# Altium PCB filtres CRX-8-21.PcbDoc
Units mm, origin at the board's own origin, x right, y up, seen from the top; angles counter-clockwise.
Board outline 63.46 x 63.5 mm, 2 copper layers (TopLayer, BottomLayer), stack 1.535 mm thick; 11 components, 6 nets, 58 pads, 970 vias.
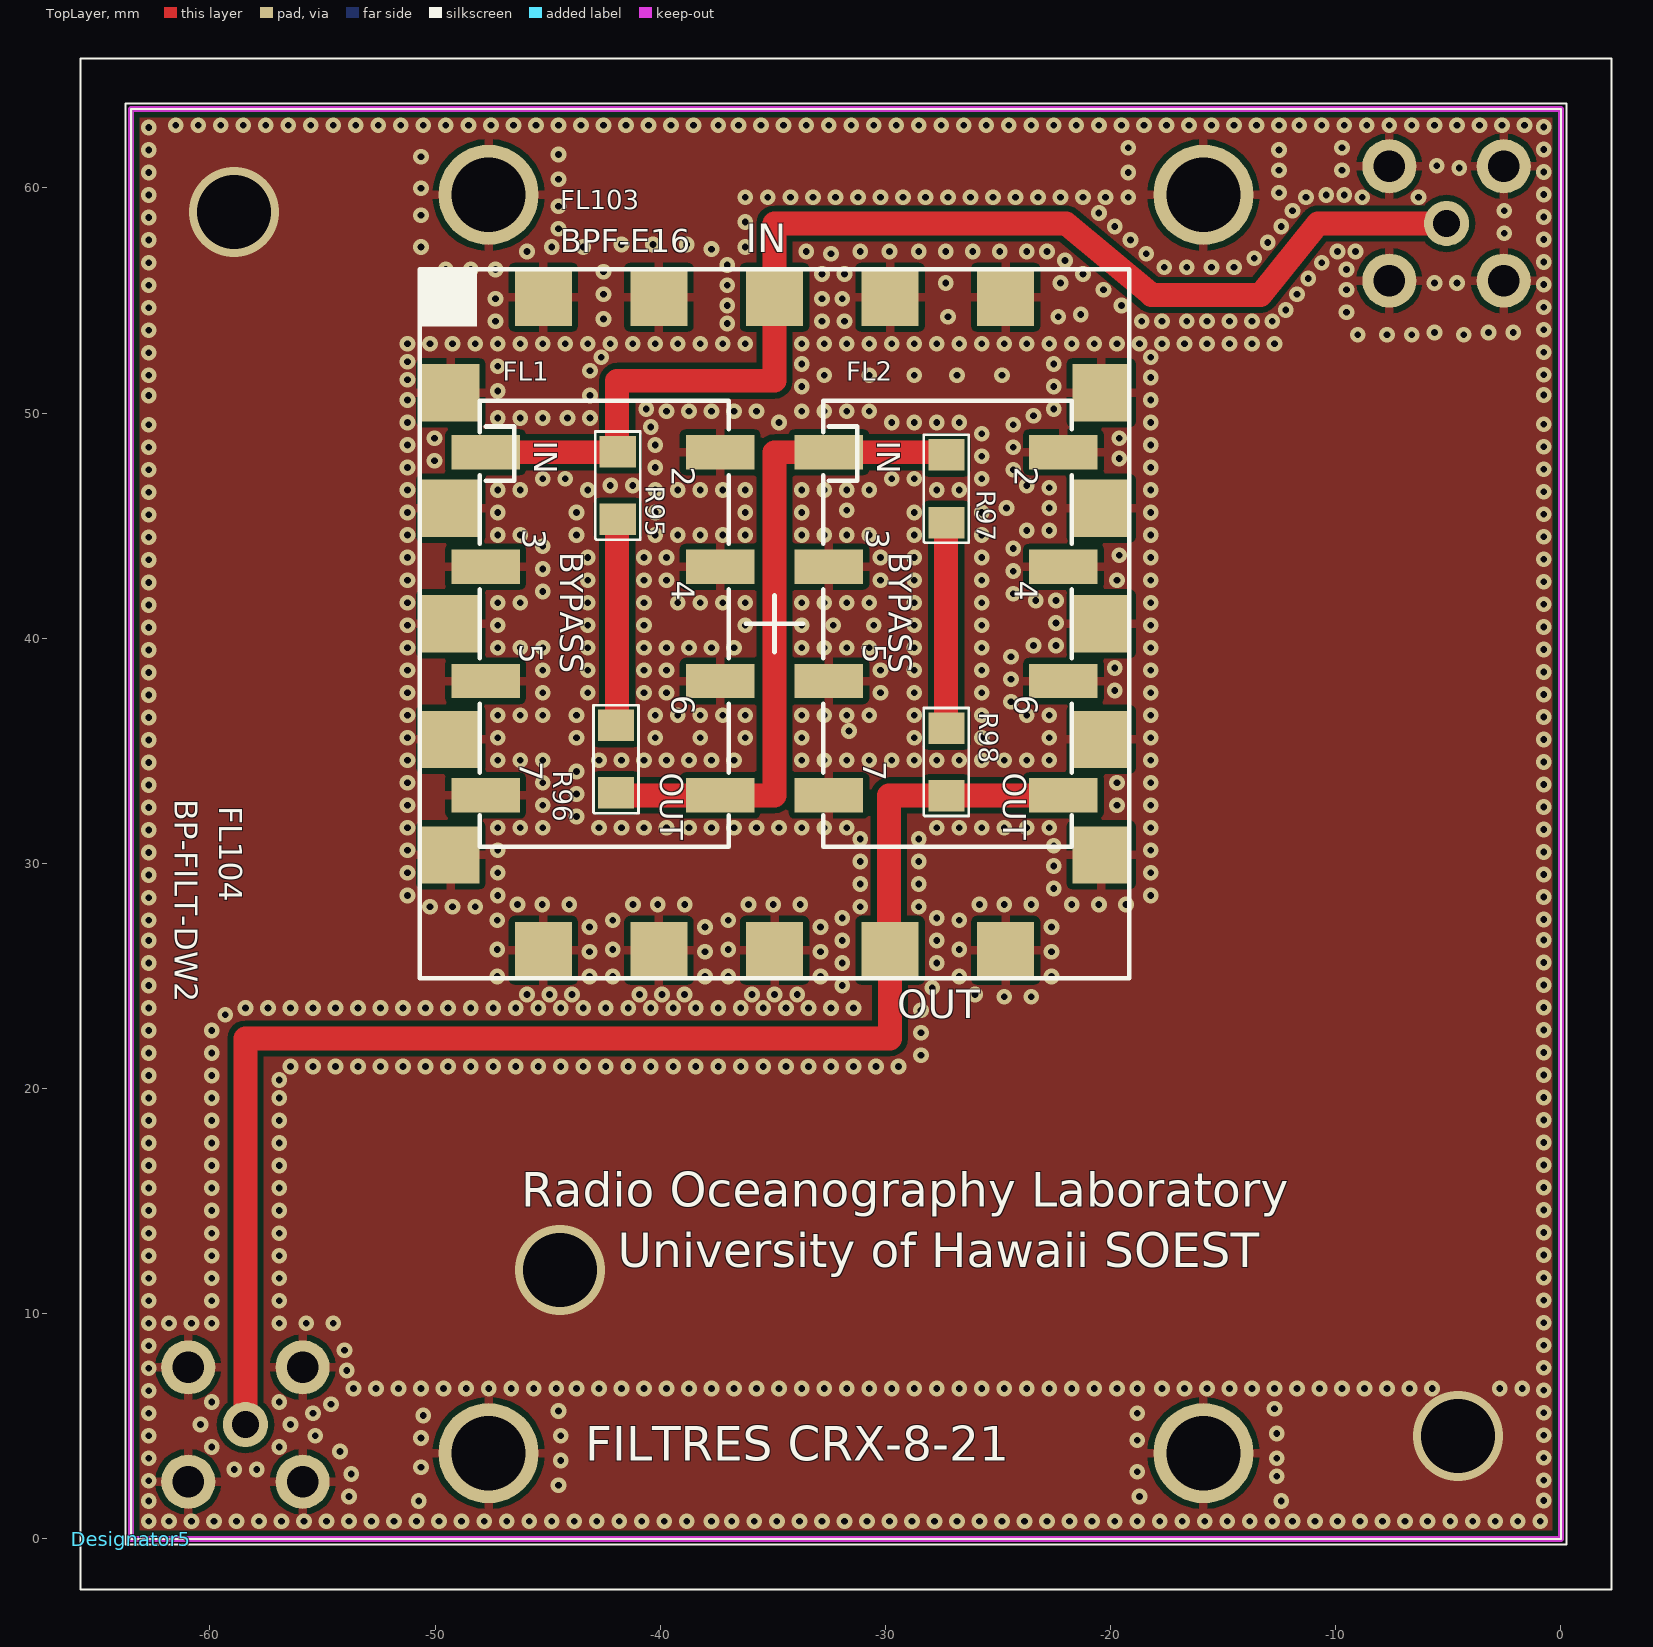
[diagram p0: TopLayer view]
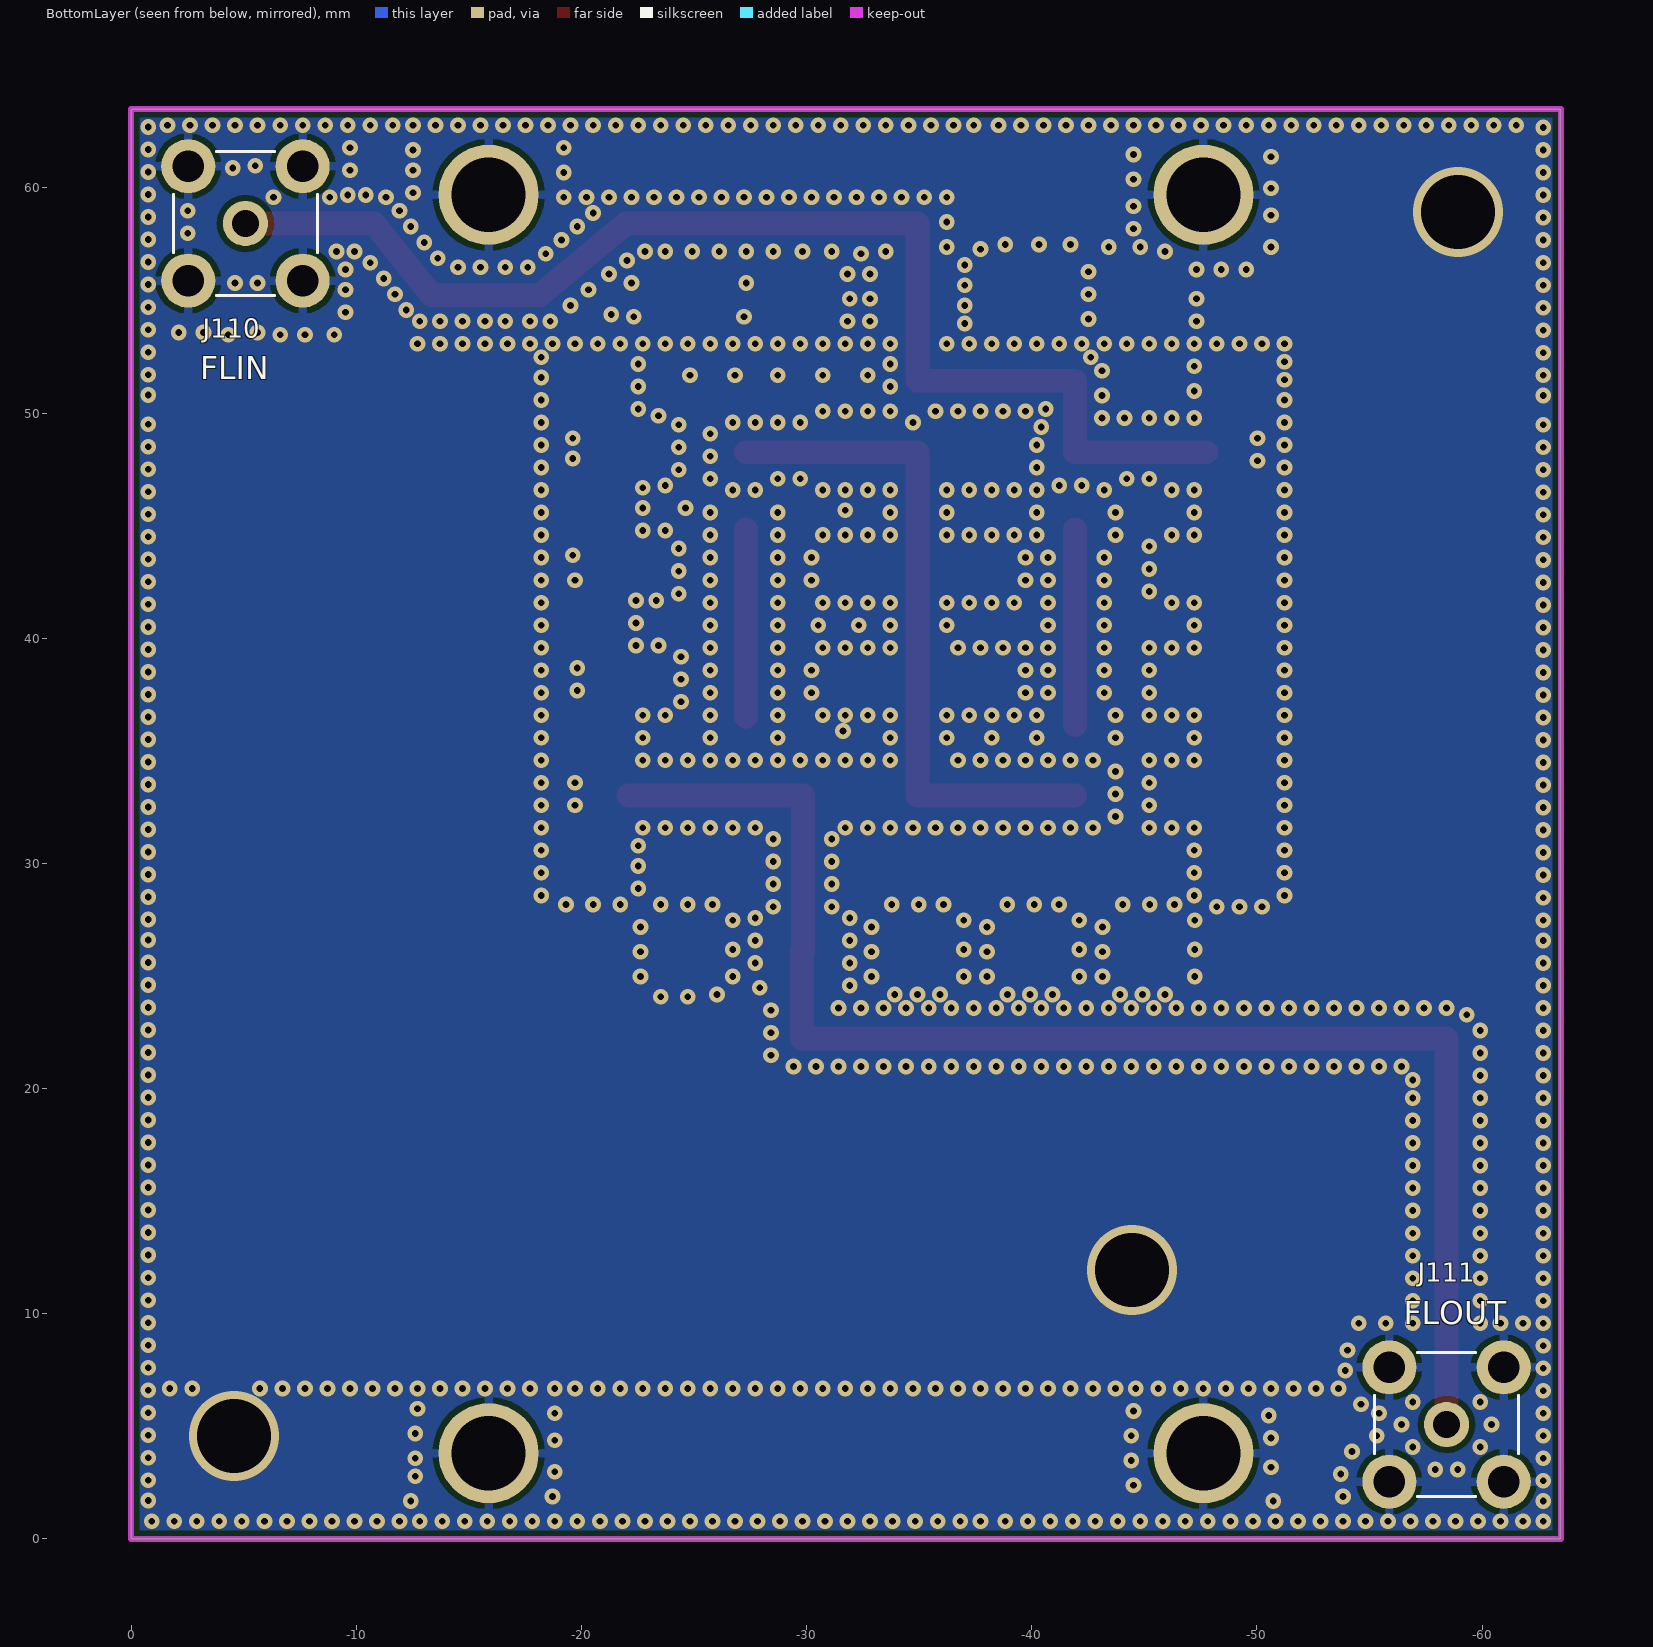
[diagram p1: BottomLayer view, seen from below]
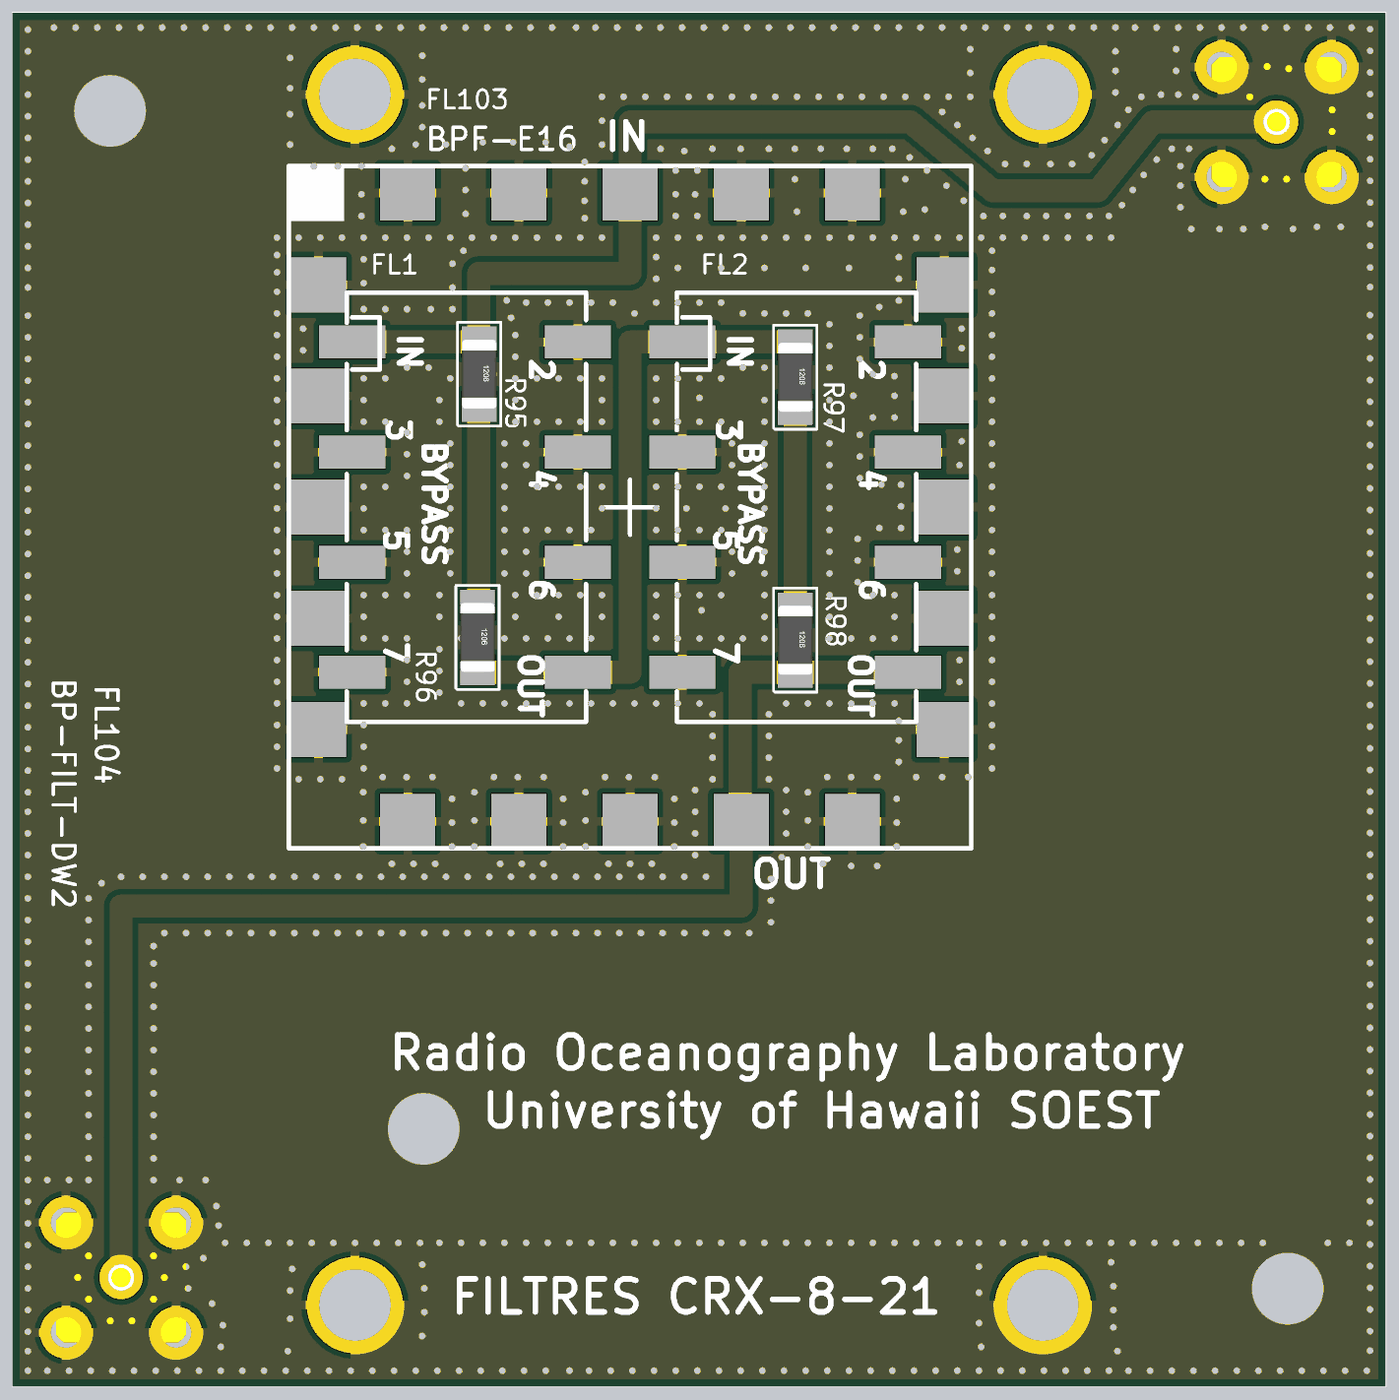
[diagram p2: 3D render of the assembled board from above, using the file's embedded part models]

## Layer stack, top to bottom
TopSolder: solder mask 0.02, Solder Resist, Dk 4
TopLayer: signal copper 0.035
Dielectric1: dielectric 1.465, FR-4, Dk 4.74
BottomLayer: signal copper 0.035
BottomSolder: solder mask 0.02, Solder Resist, Dk 4

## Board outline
-63.463,0 -63.463,63.5 0,63.5 0,0

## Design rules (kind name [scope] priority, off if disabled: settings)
Clearance Clearance_4 [InNet('RF') vs InPolygon] p1: gap=0.55 ignorepadtopadclearanceinfootprint=FALSE
Clearance Clearance_2 [InNet('RF') vs InPolygon] p2: gap=0.55 ignorepadtopadclearanceinfootprint=FALSE
Clearance Clearance_3 [InNet('RF') vs InPolygon] p3: gap=0.55 ignorepadtopadclearanceinfootprint=FALSE
Clearance Clearance_1 [InPolygon] p4: gap=0.257 ignorepadtopadclearanceinfootprint=FALSE
Clearance [InNet('rfi2x') vs InPolygon] p5: gap=0.55 ignorepadtopadclearanceinfootprint=FALSE
ComponentClearance [All] p1 off: gap=0.254 collisioncheckmode=3 verticalgap=0.254 showdistances=FALSE
FabricationTestPointUsage TestPointUsage [All] p1: valid=0 allowmultiple=FALSE
FabricationTestpoint Testpoint [All] p1: side=3 testpointundercomponent=TRUE minsize=1.016 maxsize=2.54 preferedsize=1.524 minholesize=0.508 maxholesize=1.016 preferedholesize=0.813 testpointgrid=0.025 allowsidetop=TRUE allowsidebottom=TRUE usegrid=TRUE gridtolerance=0
HoleSize [All] p1: absolutevalues=TRUE maxlimit=10 minlimit=0.025 maxpercent=80.000 minpercent=20.000
PlaneClearance PlaneClearance_15 [HasPad('TP88-TP')] p1 off: clearance=1.27
PlaneClearance PlaneClearance_16 [HasPad('TP85-TP')] p2 off: clearance=1.27
PlaneClearance PlaneClearance_13 [HasPad('TP86-TP')] p3 off: clearance=1.27
PlaneClearance PlaneClearance_14 [HasPad('TP84-TP')] p4 off: clearance=1.27
PlaneClearance PlaneClearance_17 [HasPad('TP81-TP')] p5 off: clearance=1.27
PlaneClearance PlaneClearance_20 [HasPad('TP99-TP')] p6 off: clearance=1.27
PlaneClearance PlaneClearance_21 [HasPad('TP83-TP')] p7 off: clearance=1.27
PlaneClearance PlaneClearance_18 [HasPad('TP87-TP')] p8 off: clearance=1.27
PlaneClearance PlaneClearance_19 [HasPad('TP82-TP')] p9 off: clearance=1.27
PlaneClearance PlaneClearance_4 [HasPad('TPQ3-TP')] p10 off: clearance=0.381
PlaneClearance PlaneClearance_5 [HasPad('TP8-TP')] p11 off: clearance=0.381
PlaneClearance PlaneClearance_6 [HasPad('TP14-TP')] p12 off: clearance=0.381
PlaneClearance PlaneClearance_1 [HasPad('TP3-TP')] p13 off: clearance=0.381
PlaneClearance PlaneClearance_2 [HasPad('TP2-TP')] p14 off: clearance=0.381
PlaneClearance PlaneClearance_3 [HasPad('TP1-TP')] p15 off: clearance=0.381
PlaneClearance PlaneClearance_10 [HasPad('TP5-TP')] p16 off: clearance=0.381
PlaneClearance PlaneClearance_11 [HasPad('TP12-TP')] p17 off: clearance=0.381
PlaneClearance PlaneClearance_12 [HasPad('TP108-TP')] p18 off: clearance=0.381
PlaneClearance PlaneClearance_7 [HasPad('TPQ14-TP')] p19 off: clearance=0.381
PlaneClearance PlaneClearance_8 [HasPad('TP9-TP')] p20 off: clearance=0.381
PlaneClearance PlaneClearance_9 [HasPad('TPQ5-TP')] p21 off: clearance=0.381
PlaneClearance [All] p22 off: clearance=0.254
PlaneConnect PlaneConnect_1 [All] p1 off: planeconnectstyle=Relief reliefexpansion=0.508 reliefentries=4 reliefconductorwidth=0.254 reliefairgap=0.254
PlaneConnect [All] p2 off: planeconnectstyle=Relief reliefexpansion=0.508 reliefentries=4 reliefconductorwidth=0.254 reliefairgap=0.254
PolygonConnect PolygonConnect_1 [IsVia] p1 off: connectstyle=Direct reliefconductorwidth=0.254 reliefentries=4 polygonreliefangle="90 Angle" airgapwidth=0.254
PolygonConnect PolygonConnect_2 [All] p2: thpad.connectstyle=Relief thpad.reliefconductorwidth=0.4 thpad.reliefentries=4 thpad.polygonreliefangle="90 Angle" thpad.airgapwidth=0.257 smdpad.connectstyle=Relief smdpad.reliefconductorwidth=0.4 smdpad.reliefentries=4 smdpad.polygonreliefangle="90 Angle" smdpad.airgapwidth=0.257 via.connectstyle=Direct via.reliefconductorwidth=0.254 via.reliefentries=4 via.polygonreliefangle="90 Angle" via.airgapwidth=0.254
PolygonConnect [All] p3 off: connectstyle=Relief reliefconductorwidth=0.254 reliefentries=4 polygonreliefangle="90 Angle" airgapwidth=0.257
RoomDefinition LNA [InComponentClass('LNA')] p1: confinementstyle=ConfineIn formatcopy=TRUE lockcomponents=FALSE outline -963.715,-1402.208 -912.915,-1402.208 -912.915,-1376.808 -963.715,-1376.808
RoutingPriority [All] p1: routingpriority=2
RoutingVias [All] p1: holewidth=0.3 width=0.7 viastyle="Through Hole" minholewidth=0.3 minwidth=0.7 maxholewidth=1.1 maxwidth=2
SilkToSilkClearance [All] p1 off: silktosilkclearance=0.254
SilkToSolderMaskClearance [IsPad] p1 off: minsilkscreentomaskgap=0.254 clearancetoexposedcopper=TRUE
SolderMaskExpansion [All] p1: expansion=0.051
UnpouredPolygon [All] p1 off:
Width [All] p1: maxlimit=10 minlimit=0.2 preferedwidth=0.635 bottomlayer_minwidth=0.254 minimp=50.000000 maximp=50.000000 favimp=50.000000
20 further rules are at their usual default settings.

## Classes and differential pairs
component class LNA: FL1 FL2 FL103 FL104 J110 J111 R95 R96 R97 R98

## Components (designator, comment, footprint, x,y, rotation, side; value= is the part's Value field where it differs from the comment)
Designator5 "Comment" couvfiltre -63.5,0 r0 top
FL1 "SXBP-27R5" FILTX2 -42.545,40.64 r270 top
FL2 "SXLP-30" FILTX2 -27.305,40.64 r270 top
FL103 "BPF-E16" HR1176 -34.925,40.64 r270 top
FL104 "BP-FILT-DW2" BP-FILT-DW2 -31.75,31.75 r90 top
J110 "FLIN" MCX-P-P-H-ST-TH2 -5.08,58.42 r180 bottom
J111 "FLOUT" MCX-P-P-H-ST-TH2 -58.42,5.08 r180 bottom
R95 "ZERO" R1206 -41.887,46.779 r270 top
R96 "ZERO" R1206 -41.965,34.628 r270 top
R97 "ZERO" R1206 -27.296,46.638 r270 top
R98 "ZERO" R1206 -27.296,34.503 r270 top

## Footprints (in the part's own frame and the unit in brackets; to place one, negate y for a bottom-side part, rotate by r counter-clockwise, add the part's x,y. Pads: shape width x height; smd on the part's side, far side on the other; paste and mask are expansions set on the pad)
BP-FILT-DW2 [mm]
  round 4.445 hole 3.3: 5(-27.94,15.875) 6(-27.94,-15.875) 7(27.94,15.875) 8(27.94,-15.875)
couvfiltre [mm]
  silkscreen extent -2.25,-2.25 65.75,65.75
FILTX2 [mil]
  rect 60x120 smd: 1(-300,-205) 2(-300,205) 3(-100,-205) 4(-100,205) 5(100,-205) 6(100,205) 7(300,-205) 8(300,205)
  silkscreen extent -390,-215 390,220
HR1176 [mil]
  rect 100x100 smd: 1(-404,-566) 2(-202,-566) 3(0,-566) 4(202,-566) 5(404,-566) 6(571,-404) 7(571,-202) 8(571,0) 9(571,202) 10(571,404) 11(404,571) 12(202,571) 13(0,571) 14(-202,571) 15(-404,571) 16(-571,404) 17(-571,202) 18(-571,0) 19(-571,-202) 20(-571,-404)
  silkscreen extent -620,-620 620,620
MCX-P-P-H-ST-TH2 [mm]
  round 2 hole 1.2: 1(0,0)
  round 2.4 hole 1.4: 2(-2.54,2.54) 3(2.54,2.54) 4(-2.54,-2.54) 5(2.54,-2.54)
  silkscreen extent -3.2,-3.2 3.2,3.2, body extent -3,-3 3,3, height 11.2
R1206 [mm]
  rect 1.4x1.6 smd mask+0.05: 1(-1.5,0) 2(1.5,0)
  silkscreen extent -2.4,-1 2.4,1, body extent -1.6,-0.8 1.6,0.8, height 1

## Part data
FL1: library part "LP FILTER_1", MFR=MCI, MFR PART=SXBP-27R5+
FL2: library part "LP FILTER_1", MFR=MCI, MFR PART=SXLP-30+
FL103: MFR=MCI, MFR PART=BPF-E16+
FL104: library part BP-FILTER-DW_1
J110 J111: library part SMA-4G, MFR="Cinch Connectivity Solutions Johnson", MFR PART=133-3701-211
R95 R96 R97 R98: library part R1206, MFR=Yageo, MFR PART=RC1206JR-070RL

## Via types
v1: diameter 0.7, hole 0.3, TopLayer to BottomLayer, 967 vias
v2: diameter 4, hole 3.3, TopLayer to BottomLayer, 3 vias

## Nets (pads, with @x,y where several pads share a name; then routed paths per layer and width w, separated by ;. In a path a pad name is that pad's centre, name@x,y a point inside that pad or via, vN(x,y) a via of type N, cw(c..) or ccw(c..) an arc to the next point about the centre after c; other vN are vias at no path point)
BP2: R95.2 R96.1 | length 8.7
  TopLayer w1.064: R96.1@-41.91,36.145 R95.2@-41.91,44.831
BP3: FL1.8 FL2.1 R96.2 R97.1 | length 29.8
  TopLayer w1.064: R96.2@-41.91,33.02 FL1.8 -34.925,33.02 -34.925,48.26 FL2.1 R97.1@-27.305,48.26
BP4: R97.2 R98.1 | length 8.3
  TopLayer w1.064: R98.1@-27.305,36.512 R97.2@-27.305,44.831
GND: FL1.2 FL1.3 FL1.4 FL1.5 FL1.6 FL1.7 FL2.2 FL2.3 FL2.4 FL2.5 FL2.6 FL2.7 FL103.1 FL103.2 FL103.3 FL103.4 FL103.5 FL103.6 FL103.7 FL103.8 FL103.10 FL103.11 FL103.12 FL103.13 FL103.14 FL103.15 FL103.16 FL103.17 FL103.19 FL103.20 FL104.5 FL104.6 FL104.7 FL104.8 J110.2 J110.3 J110.4 J110.5 J111.2 J111.3 J111.4 J111.5
  other v1: -62.72,0.78 -61.82,0.78 -60.82,0.78 -59.82,0.78 -58.82,0.78 -57.82,0.78 -56.82,0.78 -55.82,0.78 -54.82,0.78 -53.82,0.78 -52.82,0.78 -51.82,0.78 -50.82,0.78 -49.82,0.78 -48.82,0.78 -47.82,0.78 -46.82,0.78 -45.82,0.78 -44.82,0.78 -43.82,0.78 -42.82,0.78 -41.82,0.78 -40.82,0.78 -39.82,0.78 -38.82,0.78 -37.72,0.78 -36.82,0.78 -35.82,0.78 -34.82,0.78 -33.82,0.78 -32.82,0.78 -31.82,0.78 -30.82,0.78 -29.82,0.78 -28.82,0.78 -27.82,0.78 -26.82,0.78 -25.82,0.78 -24.82,0.78 -23.82,0.78 -22.82,0.78 -21.82,0.78 -20.82,0.78 -19.82,0.78 -18.82,0.78 -17.82,0.78 -16.82,0.78 -15.82,0.78 -14.82,0.78 -13.82,0.78 -12.82,0.78 -11.92,0.78 -10.92,0.78 -9.92,0.78 -8.92,0.78 -7.92,0.78 -6.92,0.78 -5.92,0.78 -4.92,0.78 -3.92,0.78 -2.92,0.78 -1.92,0.78 -0.92,0.78 -62.72,1.68 -50.72,1.68 -12.42,1.68 -0.768,1.704 -53.82,1.88 -18.72,1.88 -44.52,2.38 -62.72,2.58 -0.768,2.604 -12.62,2.78 -53.72,2.88 -18.82,2.98 -58.92,3.08 -57.92,3.08 -50.62,3.18 -44.42,3.48 -62.72,3.58 -12.62,3.58 -0.768,3.604 -54.22,3.88 -59.92,4.08 -56.92,4.08 -18.82,4.38 -50.62,4.48 -62.72,4.58 -55.32,4.58 -44.42,4.58 -0.768,4.604 -12.62,4.68 -60.42,5.08 -56.42,5.08 -50.52,5.48 -62.72,5.58 -55.42,5.58 -18.82,5.58 -0.768,5.604 -44.52,5.68 -12.72,5.78 -54.62,5.98 -59.92,6.08 -56.92,6.08 -62.72,6.58 -0.768,6.604 -53.62,6.68 -52.62,6.68 -51.62,6.68 -50.62,6.68 -49.62,6.68 -48.62,6.68 -47.62,6.68 -46.62,6.68 -45.62,6.68 -44.62,6.68 -43.72,6.68 -42.72,6.68 -41.72,6.68 -40.72,6.68 -39.72,6.68 -38.72,6.68 -37.72,6.68 -36.72,6.68 -35.72,6.68 -34.72,6.68 -33.72,6.68 -32.72,6.68 -31.72,6.68 -30.72,6.68 -29.72,6.68 -28.72,6.68 -27.72,6.68 -26.72,6.68 -25.72,6.68 -24.72,6.68 -23.72,6.68 -22.72,6.68 -21.72,6.68 -20.72,6.68 -19.72,6.68 -18.82,6.68 -17.72,6.68 -16.72,6.68 -15.72,6.68 -14.72,6.68 -13.72,6.68 -12.72,6.68 -11.72,6.68 -10.72,6.68 -9.72,6.68 -8.72,6.68 -7.72,6.68 -6.72,6.68 -5.72,6.68 -2.72,6.68 -1.72,6.68 -53.92,7.48 -62.72,7.58 -0.768,7.604 -54.02,8.38 -62.72,8.58 -0.768,8.604 -62.72,9.58 -61.82,9.58 -60.82,9.58 -59.92,9.58 -56.92,9.58 -55.72,9.58 -54.52,9.58 -0.768,9.604 -62.72,10.58 -59.92,10.58 -56.92,10.58 -0.768,10.604 -62.72,11.58 -59.92,11.58 -56.92,11.58 -0.768,11.604 -62.72,12.58 -59.92,12.58 -56.92,12.58 -0.768,12.604 -62.72,13.58 -59.92,13.58 -56.92,13.58 -0.768,13.604 -62.72,14.58 -59.92,14.58 -56.92,14.58 -0.768,14.604 -62.72,15.58 -59.92,15.58 -56.92,15.58 -0.768,15.604 -62.72,16.58 -59.92,16.58 -56.92,16.58 -0.768,16.604 -62.72,17.58 -59.92,17.58 -56.92,17.58 -0.768,17.604 -62.72,18.58 -59.92,18.58 -56.92,18.58 -0.768,18.604 -62.72,19.58 -59.92,19.58 -56.92,19.58 -0.768,19.604 -56.92,20.38 -62.72,20.58 -59.92,20.58 -0.768,20.604 -56.42,20.98 -55.42,20.98 -54.42,20.98 -53.42,20.98 -52.42,20.98 -51.42,20.98 -50.42,20.98 -49.42,20.98 -48.42,20.98 -47.42,20.98 -46.42,20.98 -45.42,20.98 -44.42,20.98 -43.42,20.98 -42.42,20.98 -41.42,20.98 -40.42,20.98 -39.42,20.98 -38.42,20.98 -37.42,20.98 -36.42,20.98 -35.42,20.98 -34.42,20.98 -33.42,20.98 -32.42,20.98 -31.42,20.98 -30.42,20.98 -29.42,20.98 -28.42,21.48 -62.72,21.58 -59.92,21.58 -0.768,21.604 -28.42,22.48 -62.72,22.58 -59.92,22.58 -0.768,22.604 -59.32,23.28 -28.42,23.48 -62.72,23.58 -58.42,23.58 -57.42,23.58 -56.42,23.58 -55.42,23.58 -54.42,23.58 -53.42,23.58 -52.42,23.58 -51.42,23.58 -50.42,23.58 -49.42,23.58 -48.42,23.58 -47.42,23.58 -46.42,23.58 -45.42,23.58 -44.42,23.58 -43.42,23.58 -42.42,23.58 -41.42,23.58 -40.42,23.58 -39.42,23.58 -38.42,23.58 -37.42,23.58 -36.42,23.58 -35.42,23.58 -34.42,23.58 -33.42,23.58 -32.42,23.58 -31.42,23.58 -0.768,23.604 -24.72,24.08 -23.52,24.08 -45.92,24.18 -44.92,24.18 -43.92,24.18 -40.92,24.18 -39.92,24.18 -38.92,24.18 -35.92,24.18 -34.92,24.18 -33.92,24.18 -26.02,24.18 -27.92,24.48 -62.72,24.58 -31.92,24.58 -0.768,24.604 -47.243,24.98 -43.143,24.98 -42.112,24.98 -38.012,24.98 -36.982,24.98 -32.882,24.98 -26.72,24.98 -22.62,24.98 -62.72,25.58 -31.92,25.58 -27.72,25.58 -0.768,25.604 -43.143,26.08 -38.012,26.08 -32.882,26.08 -22.62,26.08 -47.243,26.18 -42.112,26.18 -36.982,26.18 -26.72,26.18 -62.72,26.58 -31.92,26.58 -27.72,26.58 -0.768,26.604 -43.143,27.18 -38.012,27.18 -32.882,27.18 -22.62,27.18 -62.72,27.48 -47.243,27.48 -42.112,27.48 -36.982,27.48 -26.72,27.48 -0.768,27.504 -31.92,27.58 -27.72,27.58 -50.22,28.08 -49.22,28.08 -48.22,28.08 -31.12,28.08 -28.52,28.08 -46.343,28.18 -45.243,28.18 -44.043,28.18 -41.212,28.18 -40.112,28.18 -38.912,28.18 -36.082,28.18 -34.982,28.18 -33.782,28.18 -25.82,28.18 -24.72,28.18 -23.52,28.18 -21.72,28.18 -20.52,28.18 -19.32,28.18 -62.72,28.48 -0.768,28.504 -51.22,28.58 -47.22,28.58 -18.22,28.58 -22.52,28.88 -31.12,29.08 -28.52,29.08 -62.72,29.48 -0.768,29.504 -51.22,29.58 -47.22,29.58 -18.22,29.58 -22.52,29.88 -31.12,30.08 -28.52,30.08 -62.72,30.48 -0.768,30.504 -51.22,30.58 -47.22,30.58 -18.22,30.58 -22.52,30.78 -31.12,31.08 -28.52,31.08 -62.72,31.48 -0.768,31.504 -51.22,31.58 -47.22,31.58 -46.22,31.58 -45.22,31.58 -42.72,31.58 -41.72,31.58 -40.72,31.58 -39.72,31.58 -38.72,31.58 -37.72,31.58 -36.72,31.58 -35.72,31.58 -34.72,31.58 -33.72,31.58 -32.72,31.58 -31.72,31.58 -27.72,31.58 -26.72,31.58 -25.72,31.58 -24.72,31.58 -23.72,31.58 -22.72,31.58 -18.22,31.58 -43.72,32.08 -62.72,32.48 -0.768,32.504 -51.22,32.58 -45.22,32.58 -19.72,32.58 -18.22,32.58 -43.72,33.08 -62.72,33.48 -0.768,33.504 -51.22,33.58 -45.22,33.58 -19.72,33.58 -18.22,33.58 -43.72,34.08 -62.72,34.48 -0.768,34.504 -51.22,34.58 -47.22,34.58 -46.22,34.58 -45.22,34.58 -42.72,34.58 -41.72,34.58 -40.72,34.58 -39.72,34.58 -38.72,34.58 -37.72,34.58 -36.72,34.58 -33.72,34.58 -32.72,34.58 -31.72,34.58 -30.72,34.58 -29.72,34.58 -28.72,34.58 -27.72,34.58 -26.72,34.58 -25.72,34.58 -24.72,34.58 -23.72,34.58 -22.72,34.58 -18.22,34.58 -62.72,35.48 -0.768,35.504 -51.22,35.58 -47.22,35.58 -43.72,35.58 -40.22,35.58 -38.22,35.58 -36.22,35.58 -33.72,35.58 -28.72,35.58 -25.72,35.58 -22.72,35.58 -18.22,35.58 -31.62,35.88 -62.72,36.48 -0.768,36.504 -51.22,36.58 -47.22,36.58 -46.22,36.58 -45.22,36.58 -43.72,36.58 -40.22,36.58 -39.22,36.58 -38.22,36.58 -37.22,36.58 -36.22,36.58 -33.72,36.58 -32.72,36.58 -31.72,36.58 -30.72,36.58 -28.72,36.58 -25.72,36.58 -23.72,36.58 -22.72,36.58 -18.22,36.58 -24.42,37.18 -62.72,37.48 -0.768,37.504 -51.22,37.58 -45.22,37.58 -43.22,37.58 -40.72,37.58 -39.72,37.58 -30.22,37.58 -28.72,37.58 -25.72,37.58 -18.22,37.58 -19.82,37.68 -24.42,38.18 -62.72,38.48 -0.768,38.504 -51.22,38.58 -45.22,38.58 -43.22,38.58 -40.72,38.58 -39.72,38.58 -30.22,38.58 -28.72,38.58 -25.72,38.58 -18.22,38.58 -19.82,38.68 -24.42,39.18 -62.72,39.48 -0.768,39.504 -51.22,39.58 -47.22,39.58 -46.22,39.58 -45.22,39.58 -43.22,39.58 -40.72,39.58 -39.72,39.58 -38.72,39.58 -37.72,39.58 -36.72,39.58 -33.72,39.58 -32.72,39.58 -31.72,39.58 -30.72,39.58 -28.72,39.58 -25.72,39.58 -18.22,39.58 -23.42,39.68 -22.42,39.68 -62.72,40.48 -0.768,40.504 -51.22,40.58 -47.22,40.58 -43.22,40.58 -40.72,40.58 -36.22,40.58 -33.72,40.58 -32.32,40.58 -30.52,40.58 -28.72,40.58 -25.72,40.58 -18.22,40.58 -22.42,40.68 -62.72,41.48 -0.768,41.504 -51.22,41.58 -47.22,41.58 -46.22,41.58 -43.22,41.58 -40.72,41.58 -39.22,41.58 -38.22,41.58 -37.22,41.58 -36.22,41.58 -33.72,41.58 -32.72,41.58 -31.72,41.58 -30.72,41.58 -28.72,41.58 -25.72,41.58 -18.22,41.58 -23.32,41.68 -22.42,41.68 -24.32,41.98 -45.22,42.08 -62.72,42.48 -0.768,42.504 -51.22,42.58 -43.22,42.58 -40.72,42.58 -39.72,42.58 -30.22,42.58 -28.72,42.58 -25.72,42.58 -19.72,42.58 -18.22,42.58 -24.32,42.98 -45.22,43.08 -62.72,43.48 -0.768,43.504 -51.22,43.58 -43.22,43.58 -40.72,43.58 -39.72,43.58 -30.22,43.58 -28.72,43.58 -25.72,43.58 -18.22,43.58 -19.62,43.68 -24.32,43.98 -45.22,44.08 -62.72,44.48 -0.768,44.504 -51.22,44.58 -47.22,44.58 -46.22,44.58 -43.72,44.58 -40.22,44.58 -39.22,44.58 -38.22,44.58 -37.22,44.58 -36.22,44.58 -33.72,44.58 -32.72,44.58 -31.72,44.58 -30.72,44.58 -28.72,44.58 -25.72,44.58 -18.22,44.58 -23.72,44.78 -22.72,44.78 -62.72,45.48 -0.768,45.504 -51.22,45.58 -47.22,45.58 -43.72,45.58 -40.22,45.58 -36.22,45.58 -33.72,45.58 -28.72,45.58 -25.72,45.58 -18.22,45.58 -31.72,45.68 -24.62,45.78 -22.72,45.78 -62.72,46.48 -0.768,46.504 -51.22,46.58 -47.22,46.58 -46.22,46.58 -43.22,46.58 -40.22,46.58 -39.22,46.58 -38.22,46.58 -37.22,46.58 -36.22,46.58 -33.72,46.58 -32.72,46.58 -31.72,46.58 -30.72,46.58 -27.72,46.58 -26.72,46.58 -18.22,46.58 -22.72,46.68 -42.22,46.78 -41.22,46.78 -23.72,46.78 -45.22,47.08 -44.22,47.08 -29.72,47.08 -28.72,47.08 -25.72,47.08 -62.72,47.48 -24.32,47.48 -0.768,47.504 -51.22,47.58 -40.22,47.58 -18.22,47.58 -50.02,47.88 -19.62,47.98 -25.72,48.08 -62.72,48.48 -24.32,48.48 -0.768,48.504 -51.22,48.58 -40.22,48.58 -18.22,48.58 -50.02,48.88 -19.62,48.88 -25.72,49.08 -40.42,49.38 -62.72,49.48 -24.32,49.48 -0.768,49.504 -51.22,49.58 -34.72,49.58 -29.72,49.58 -28.72,49.58 -27.72,49.58 -26.72,49.58 -18.22,49.58 -47.22,49.78 -46.22,49.78 -45.22,49.78 -44.12,49.78 -43.12,49.78 -23.42,49.88 -39.72,50.08 -38.72,50.08 -37.72,50.08 -36.72,50.08 -35.72,50.08 -33.72,50.08 -32.72,50.08 -31.72,50.08 -30.72,50.08 -40.62,50.18 -22.52,50.18 -51.22,50.58 -18.22,50.58 -62.72,50.78 -43.12,50.78 -0.768,50.804 -47.22,50.98 -33.72,51.18 -22.52,51.18 -51.22,51.48 -18.22,51.58 -62.72,51.68 -32.72,51.68 -30.72,51.68 -28.72,51.68 -26.82,51.68 -24.82,51.68 -0.768,51.704 -43.12,51.88 -47.22,52.08 -33.72,52.18 -22.52,52.18 -51.22,52.28 -42.62,52.48 -18.22,52.48 -62.72,52.68 -0.768,52.704 -51.22,53.08 -50.22,53.08 -49.22,53.08 -48.22,53.08 -47.22,53.08 -46.22,53.08 -45.22,53.08 -44.22,53.08 -43.22,53.08 -42.22,53.08 -41.22,53.08 -40.22,53.08 -39.22,53.08 -38.22,53.08 -37.22,53.08 -36.22,53.08 -33.72,53.08 -32.72,53.08 -31.72,53.08 -30.72,53.08 -29.72,53.08 -28.72,53.08 -27.72,53.08 -26.72,53.08 -25.72,53.08 -24.72,53.08 -23.72,53.08 -22.72,53.08 -21.72,53.08 -20.72,53.08 -19.72,53.08 -18.72,53.08 -17.72,53.08 -16.72,53.08 -15.72,53.08 -14.72,53.08 -13.72,53.08 -12.72,53.08 -9.02,53.48 -7.72,53.48 -6.62,53.48 -4.32,53.48 -5.62,53.58 -3.22,53.58 -2.12,53.58 -62.72,53.68 -0.768,53.704 -37.02,53.98 -47.32,54.08 -32.82,54.08 -31.82,54.08 -18.62,54.08 -17.72,54.08 -16.62,54.08 -15.72,54.08 -14.72,54.08 -13.72,54.08 -12.82,54.08 -42.52,54.18 -27.22,54.28 -22.32,54.28 -21.32,54.38 -9.52,54.48 -12.22,54.58 -62.72,54.68 -0.768,54.704 -37.02,54.78 -19.52,54.78 -47.32,55.08 -32.82,55.08 -31.92,55.08 -42.52,55.28 -11.72,55.28 -20.32,55.48 -9.52,55.48 -62.72,55.68 -37.02,55.68 -0.768,55.704 -27.32,55.78 -22.22,55.78 -5.62,55.78 -4.62,55.78 -11.22,55.98 -32.82,56.18 -31.82,56.18 -21.22,56.18 -42.52,56.28 -49.52,56.38 -48.42,56.38 -47.32,56.38 -9.52,56.38 -17.62,56.48 -16.62,56.48 -15.52,56.48 -14.52,56.48 -37.02,56.58 -62.72,56.68 -10.62,56.68 -0.768,56.704 -22.02,56.78 -13.62,56.88 -32.42,57.08 -18.42,57.08 -45.92,57.18 -33.52,57.18 -31.12,57.18 -29.82,57.18 -28.52,57.18 -27.32,57.18 -26.12,57.18 -24.92,57.18 -23.72,57.18 -22.82,57.18 -9.92,57.18 -9.12,57.18 -37.72,57.28 -50.62,57.38 -44.82,57.38 -43.42,57.38 -36.22,57.38 -41.72,57.48 -40.32,57.48 -38.82,57.48 -13.02,57.58 -62.72,57.68 -19.12,57.68 -0.768,57.704 -2.52,57.98 -44.52,58.18 -19.82,58.28 -12.42,58.28 -36.22,58.48 -62.72,58.68 -0.768,58.704 -50.62,58.78 -20.52,58.88 -11.92,58.98 -2.52,58.98 -44.52,59.18 -36.22,59.58 -35.22,59.58 -34.22,59.58 -33.22,59.58 -32.22,59.58 -31.22,59.58 -30.22,59.58 -29.22,59.58 -28.22,59.58 -27.22,59.58 -26.22,59.58 -25.22,59.58 -24.22,59.58 -23.22,59.58 -22.22,59.58 -21.22,59.58 -20.22,59.58 -19.22,59.58 -11.32,59.58 -8.82,59.58 -6.32,59.58 -62.72,59.68 -10.42,59.68 -9.62,59.68 -0.768,59.704 -12.52,59.78 -50.62,59.98 -44.52,60.38 -62.72,60.68 -19.22,60.68 -0.768,60.704 -12.52,60.78 -9.72,60.78 -4.52,60.88 -5.52,60.98 -50.62,61.38 -44.52,61.48 -62.72,61.68 -12.52,61.68 -0.768,61.704 -19.22,61.78 -9.72,61.78 -62.72,62.68 -0.768,62.704 -61.52,62.78 -60.52,62.78 -59.52,62.78 -58.52,62.78 -57.52,62.78 -56.52,62.78 -55.52,62.78 -54.52,62.78 -53.52,62.78 -52.52,62.78 -51.52,62.78 -50.52,62.78 -49.52,62.78 -48.52,62.78 -47.52,62.78 -46.52,62.78 -45.52,62.78 -44.52,62.78 -43.52,62.78 -42.52,62.78 -41.52,62.78 -40.52,62.78 -39.52,62.78 -38.52,62.78 -37.42,62.78 -36.52,62.78 -35.52,62.78 -34.52,62.78 -33.52,62.78 -32.52,62.78 -31.52,62.78 -30.52,62.78 -29.52,62.78 -28.52,62.78 -27.52,62.78 -26.52,62.78 -25.52,62.78 -24.52,62.78 -23.52,62.78 -22.52,62.78 -21.52,62.78 -20.52,62.78 -19.52,62.78 -18.52,62.78 -17.52,62.78 -16.52,62.78 -15.52,62.78 -14.52,62.78 -13.52,62.78 -12.52,62.78 -11.62,62.78 -10.62,62.78 -9.62,62.78 -8.62,62.78 -7.62,62.78 -6.62,62.78 -5.62,62.78 -4.62,62.78 -3.62,62.78 -2.62,62.78 -1.62,62.78
  other v2: -4.57,4.57 -44.45,11.94 -58.93,58.93
LNA3: FL1.1 FL103.18 J110.1 R95.1 | length 55.5
  TopLayer w1.064: FL1.1 -41.91,48.26 -41.91,51.435 -34.925,51.435 FL103.18 -34.925,58.42 -21.988,58.42 -18.178,55.245 -13.335,55.245 -10.795,58.42 J110.1
NetFL2_8: FL2.8 FL103.9 J111.1 R98.2 | length 64.4
  TopLayer w1.064: J111.1 -58.42,22.225 -29.845,22.225 ; FL103.9@-29.845,26.035 -29.845,33.02 FL2.8 ; -29.794,22.225 FL103.9

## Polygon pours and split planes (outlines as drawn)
GND on TopLayer "Bottom Layer-No Net" (solid, remove dead copper, pour order 2): -65.661,66.302 -65.661,-1.626 -66.33,-2.294 1.025,-2.294 2.744,-0.575 2.744,62.194 6.47,65.92
GND on BottomLayer "Bottom Layer-No Net" (solid, remove dead copper, pour order 1): -64.72,64.78 -64.72,-1.12 -63.52,-2.32 -1.02,-2.32 1.98,0.68 1.68,0.68 1.68,63.18 -0.52,65.38

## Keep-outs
KeepOutLayer:
  lines w0.254: -63.5,0 0,0 0,63.5 -63.5,63.5 -63.5,0

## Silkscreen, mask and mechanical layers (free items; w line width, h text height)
TopOverlay:
  text "BYPASS" at -44.45,43.815 h1.02 r270
  text "BYPASS" at -29.845,43.815 h1.02 r270
  text "Radio Oceanography Laboratory" at -46.178,14.743 h1.52
  text "University of Hawaii SOEST" at -41.89,12.063 h1.52
  text "FILTRES CRX-8-21" at -43.32,3.48 h1.52
TopPaste:
  rectangle: -12.764,64.871 -11.799,66.928
  rectangle: -11.062,64.871 -10.097,66.954
Mechanical4:
  lines w0.203: -54.395,51.942 -53.125,51.942 ; -53.76,51.307 -53.76,52.577
  lines w0.254: -37.885,21.462 -36.615,21.462 -37.885,21.462 ; -37.885,44.957 -36.615,44.957 -37.885,44.957 ; -37.25,20.827 -37.25,22.097 -37.25,20.827 ; -37.25,44.322 -37.25,45.592 -37.25,44.322
Mechanical 5:
  lines w0.127: -26.83,-114.961 -26.83,-106.281 ; 12.278,-99.456 129.581,-99.456 ; 12.278,-92.631 129.581,-92.631 ; 12.278,-81.54 129.581,-81.54 ; 12.278,-77.274 129.581,-77.274 ; 12.278,-73.009 129.581,-73.009 ; 12.278,-68.743 129.581,-68.743 ; 35.653,-85.806 35.653,-64.477 ; 53.151,-106.281 53.151,-85.806 ; 93.349,-85.806 93.349,-64.477 ; 112.372,-85.806 112.372,-64.477 ; 129.581,-64.477 -26.83,-64.477 ; -26.83,-106.281 129.581,-106.281 ; -26.83,-106.281 12.278,-106.281 ; -26.83,-106.281 -26.83,-64.477 ; -26.83,-64.477 12.278,-64.477 ; 12.278,-106.281 12.278,-64.477 ; 12.278,-106.281 12.278,-64.477 ; 12.278,-106.281 129.581,-106.281 ; 12.278,-106.281 12.278,-85.806 ; 12.278,-85.806 129.581,-85.806 ; 12.278,-85.806 129.581,-85.806 ; 111.513,-106.281 111.513,-92.631 ; 111.513,-106.281 129.581,-106.281 ; 111.513,-106.281 111.513,-92.631 ; 111.513,-99.456 111.513,-92.631 ; 111.513,-99.456 129.581,-99.456 ; 111.513,-99.456 111.513,-92.631 ; 111.513,-92.631 129.581,-92.631 ; 111.513,-92.631 129.581,-92.631 ; 129.581,-106.281 129.581,-92.631 ; 129.581,-106.281 129.581,-85.806 ; 129.581,-99.456 129.581,-92.631
  lines w0.5: -157.41,-114.949 -26.81,-114.949 129.59,-114.949 129.59,95.051 -157.41,95.051 -157.41,-114.949
  text "Radio / Oceanography / Laboratory" at -20.883,-79.067 h4
  text "Indice" at 16.339,-84.396 h1.76
  text "Modification" at 55.308,-84.396 h1.76
  text "Date" at 98.982,-84.396 h1.76
  text "Dessine par" at 114.537,-84.478 h1.5
  text "Edition" at 13.249,-90.407 h1.76
  text ":" at 33.188,-90.407 h1.76
  text "CARTE FILTRE CRX-8-21" at 56.99,-91.049 h1.8
  text "Dessinateur" at 13.249,-96.419 h1.76
  text "Folio" at 112.388,-96.419 h1.8
  text ":" at 33.188,-96.439 h1.76
  text ":" at 120.857,-96.439 h1.76
  text "1/1" at 123.234,-96.815 h1.76
  text "RONVEL" at 36.256,-96.93 h1.95
  text ":" at 33.188,-103.032 h1.76
  text "Date" at 13.249,-103.084 h1.76
  text "Ind" at 112.388,-103.084 h1.95
  text "06/04/21" at 35.29,-104.049 h1.8
Mechanical6:
  lines w0.127: -157.202,-81.498 -39.9,-81.498 ; -157.202,-77.233 -39.9,-77.233 ; -157.202,-72.967 -39.9,-72.967 ; -157.202,-68.702 -39.9,-68.702 ; -157.202,-64.436 -0.791,-64.436 ; -139.993,-85.764 -139.993,-64.436 ; -120.97,-85.764 -120.97,-64.436 ; -80.772,-106.239 -80.772,-85.764 ; -63.274,-85.764 -63.274,-64.436 ; -39.9,-99.414 -157.202,-99.414 ; -39.9,-92.589 -157.202,-92.589 ; -0.791,-114.919 -0.791,-106.239 ; -157.202,-106.239 -39.9,-106.239 ; -157.202,-106.239 -157.202,-85.764 ; -157.202,-106.239 -139.134,-106.239 ; -157.202,-106.239 -157.202,-92.589 ; -157.202,-106.239 -0.791,-106.239 ; -157.202,-99.414 -139.134,-99.414 ; -157.202,-99.414 -157.202,-92.589 ; -157.202,-92.589 -139.134,-92.589 ; -157.202,-92.589 -139.134,-92.589 ; -157.202,-85.764 -39.9,-85.764 ; -157.202,-85.764 -39.9,-85.764 ; -139.134,-106.239 -139.134,-92.589 ; -139.134,-106.239 -139.134,-92.589 ; -139.134,-99.414 -139.134,-92.589 ; -139.134,-99.414 -139.134,-92.589 ; -39.9,-106.239 -39.9,-85.764 ; -39.9,-106.239 -0.791,-106.239 ; -39.9,-106.239 -39.9,-64.436 ; -39.9,-106.239 -39.9,-64.436 ; -39.9,-64.436 -0.791,-64.436 ; -0.791,-106.239 -0.791,-64.436
  lines w0.5: -157.211,-114.908 -157.211,95.092 129.789,95.092 129.789,-114.908 -0.811,-114.908 -157.211,-114.908
  text "Radio" at -6.738,-70.878 h4
  text "Oceanography" at -6.738,-74.04 h4
  text "Laboratory" at -6.738,-78.272 h4
  text "Date" at -126.603,-84.354 h1.76
  text "Modification" at -82.929,-84.354 h1.76
  text "Indice" at -43.961,-84.354 h1.76
  text "Dessine par" at -142.158,-84.437 h1.5
  text ":" at -60.809,-90.366 h1.76
  text "Edition" at -40.87,-90.366 h1.76
  text "CARTE FILTRE CRX-8-21" at -84.611,-91.008 h1.8
  text "Folio" at -140.01,-96.377 h1.8
  text "Dessinateur" at -40.87,-96.377 h1.76
  text ":" at -148.479,-96.398 h1.76
  text ":" at -60.809,-96.398 h1.76
  text "1/1" at -150.855,-96.774 h1.76
  text "RONVEL" at -63.877,-96.889 h1.95
  text "PLAN DE CABLAGE BOTTOM" at -88.611,-97.508 h4
  text ":" at -60.809,-102.991 h1.76
  text "Ind" at -140.01,-103.042 h1.95
  text "Date" at -40.87,-103.042 h1.76
  text "06/04/21" at -62.911,-104.008 h1.8
Mechanical7:
  text "PLAN DE CABLAGE TOP" at 60.99,-97.549 h4
Mechanical9:
  text "PLAN DE PERCAGE" at 66.59,-97.449 h4
DrillDrawing:
  drawing of 525 lines, arcs and shapes, not listed
  text "EMPILAGE" at -86.741,-33.378 h2.5
  text "Layer" at -137.454,-38.391 h1.3
  text "Name" at -128.805,-38.391 h1.3
  text "Material" at -110.194,-38.391 h1.3
  text "Thickness" at -91.799,-38.391 h1.3
  text "Constant" at -77.953,-38.391 h1.3
  text "Board Layer Stack" at -65.839,-38.391 h1.3
  text "Board Layer Stack" at -41.812,-38.391 h1.3
  text "Board Layer Stack" at -17.786,-38.391 h1.3
  text "Board Layer Stack" at 6.241,-38.391 h1.3
  text "1" at -137.454,-40.991 h1.3
  text "TopOverlay" at -128.805,-40.991 h1.3
  text "2" at -137.454,-43.591 h1.3
  text "TopSolder" at -128.805,-43.591 h1.3
  text "Solder Resist" at -110.194,-43.591 h1.3
  text "0,020mm" at -91.799,-43.591 h1.3
  text "4" at -77.953,-43.591 h1.3
  text "3" at -137.454,-46.191 h1.3
  text "TopLayer" at -128.805,-46.191 h1.3
  text "Copper" at -110.194,-46.191 h1.3
  text "0,035mm" at -91.799,-46.191 h1.3
  text "MATIERE FR4 ( voir empilage) / CUIVRE 35 Microns 2 faces / TECHNO DOUBLE FACE / VERNIS SELECTIF VERT 2 FACES / SERIGRAPHIE BLANCHE 2 FACES / FINITION NiAu" at 43.074,-46.36 h1.52
  text "4" at -137.454,-48.791 h1.3
  text "Dielectric1" at -128.805,-48.791 h1.3
  text "FR-4" at -110.194,-48.791 h1.3
  text "1,465mm" at -91.799,-48.791 h1.3
  text "4,74" at -77.953,-48.791 h1.3
  text "5" at -137.454,-51.391 h1.3
  text "BottomLayer" at -128.805,-51.391 h1.3
  text "Copper" at -110.194,-51.391 h1.3
  text "0,035mm" at -91.799,-51.391 h1.3
  text "6" at -137.454,-53.991 h1.3
  text "BottomSolder" at -128.805,-53.991 h1.3
  text "Solder Resist" at -110.194,-53.991 h1.3
  text "0,020mm" at -91.799,-53.991 h1.3
  text "4" at -77.953,-53.991 h1.3
  text "7" at -137.454,-56.591 h1.3
  text "BottomOverlay" at -128.805,-56.591 h1.3
  text "IMPEDANCE / PISTES 1.064mm 50 ohms" at 43.074,-57.899 h1.52
  text "Symbol" at -150.846,-89.16 h1.5
  text "Count" at -140.163,-89.16 h1.5
  text "Hole Size" at -127.579,-89.16 h1.5
  text "Plated" at -103.126,-89.16 h1.5
  text "Hole Type" at -92.444,-89.16 h1.5
  text "Drill Layer Pair" at -77.014,-89.16 h1.5
  text "Via/Pad" at -48.189,-89.16 h1.5
  text "2" at -140.163,-92.284 h1.25
  text "1,200mm (47,24mil)" at -127.579,-92.284 h1.25
  text "PTH" at -103.126,-92.284 h1.25
  text "Round" at -92.444,-92.284 h1.25
  text "TopLayer - BottomLayer" at -77.014,-92.284 h1.25
  text "Pad" at -48.189,-92.284 h1.25
  text "7" at -140.163,-95.408 h1.25
  text "3,300mm (129,92mil)" at -127.579,-95.408 h1.25
  text "PTH" at -103.126,-95.408 h1.25
  text "Round" at -92.444,-95.408 h1.25
  text "TopLayer - BottomLayer" at -77.014,-95.408 h1.25
  text "(Mixed)" at -48.189,-95.408 h1.25
  text "8" at -140.163,-98.532 h1.25
  text "1,400mm (55,12mil)" at -127.579,-98.532 h1.25
  text "PTH" at -103.126,-98.532 h1.25
  text "Round" at -92.444,-98.532 h1.25
  text "TopLayer - BottomLayer" at -77.014,-98.532 h1.25
  text "Pad" at -48.189,-98.532 h1.25
  text "967" at -140.163,-101.656 h1.25
  text "0,300mm (11,81mil)" at -127.579,-101.656 h1.25
  text "PTH" at -103.126,-101.656 h1.25
  text "Round" at -92.444,-101.656 h1.25
  text "TopLayer - BottomLayer" at -77.014,-101.656 h1.25
  text "Via" at -48.189,-101.656 h1.25
  text "984 Total" at -140.163,-104.781 h1.25

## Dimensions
-63.5,0 to 0,0 on DrillDrawing
-63.463,0 to -63.5,63.5 on DrillDrawing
